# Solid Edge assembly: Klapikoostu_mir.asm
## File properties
Author: Türk
Template: Iso Assembly.asm
Last saved by: Türk
Revision: 3
Application: Solid Edge
Username: Türk
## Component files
Klapipuks.par
Klapp.par
Klapi vedru_mir.par
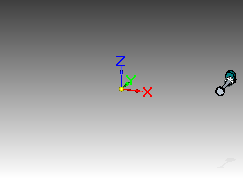
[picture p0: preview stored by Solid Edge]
